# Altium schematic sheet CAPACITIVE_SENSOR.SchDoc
size A4; Revision: V1.2; SheetNumber: 4; SheetTotal: 10
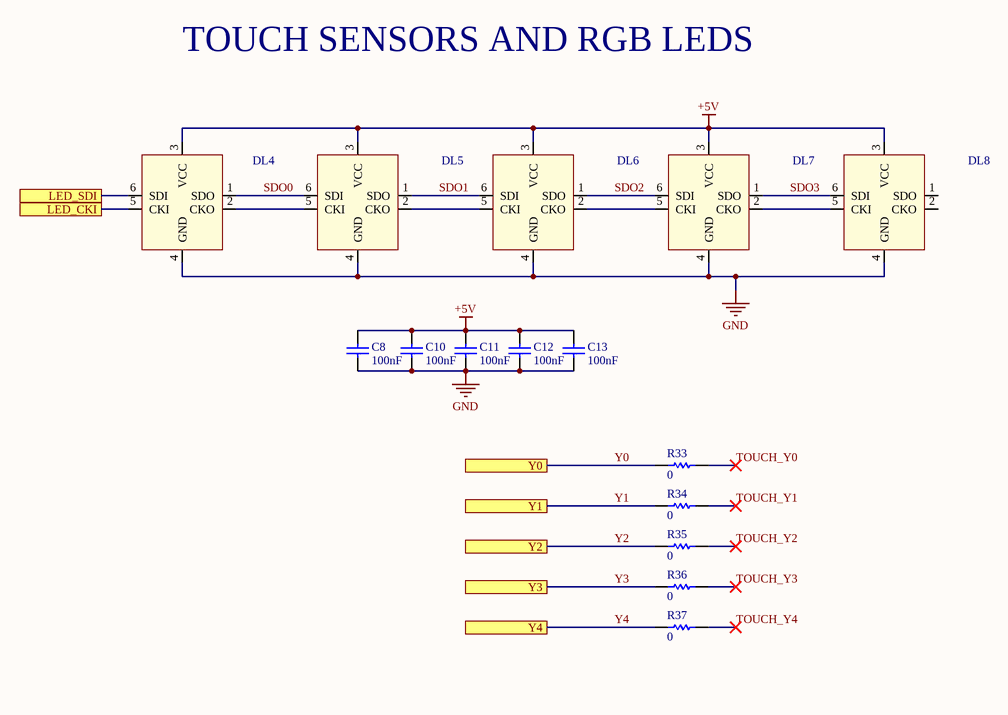
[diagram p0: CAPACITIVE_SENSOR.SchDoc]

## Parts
C8  value 100nF  [CAP-0402]  (hidden comment: GRM155R61H104KE19D)
C10  value 100nF  [CAP-0402]  (hidden comment: GRM155R61H104KE19D)
C11  value 100nF  [CAP-0402]  (hidden comment: GRM155R61H104KE19D)
C12  value 100nF  [CAP-0402]  (hidden comment: GRM155R61H104KE19D)
C13  value 100nF  [CAP-0402]  (hidden comment: GRM155R61H104KE19D)
DL4  APA1022020-2018  [APA102-2020-Footprint-1]  (value not drawn)
DL5  APA1022020-2018  [APA102-2020-Footprint-1]  (value not drawn)
DL6  APA1022020-2018  [APA102-2020-Footprint-1]  (value not drawn)
DL7  APA1022020-2018  [APA102-2020-Footprint-1]  (value not drawn)
DL8  APA1022020-2018  [APA102-2020-Footprint-1]  (value not drawn)
R33  value 0  [RES-0402]  (hidden comment: CRCW04020000Z0EDC)
R34  value 0  [RES-0402]  (hidden comment: CRCW04020000Z0EDC)
R35  value 0  [RES-0402]  (hidden comment: CRCW04020000Z0EDC)
R36  value 0  [RES-0402]  (hidden comment: CRCW04020000Z0EDC)
R37  value 0  [RES-0402]  (hidden comment: CRCW04020000Z0EDC)

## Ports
LED_CKI, LED_SDI, Y0, Y1, Y2, Y3, Y4

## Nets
+5V: C8.2 C10.2 C11.2 C12.2 C13.2 DL4.3(VCC) DL5.3(VCC) DL6.3(VCC) DL7.3(VCC) DL8.3(VCC)
GND: C8.1 C10.1 C11.1 C12.1 C13.1 DL4.4(GND) DL5.4(GND) DL6.4(GND) DL7.4(GND) DL8.4(GND)
LED_CKI: DL4.5(CKI) ; port LED_CKI
LED_SDI: DL4.6(SDI) ; port LED_SDI
SDO0: DL4.1(SDO) DL5.6(SDI)
SDO1: DL5.1(SDO) DL6.6(SDI)
SDO2: DL6.1(SDO) DL7.6(SDI)
SDO3: DL7.1(SDO) DL8.6(SDI)
TOUCH_Y0: R33.2
TOUCH_Y1: R34.2
TOUCH_Y2: R35.2
TOUCH_Y3: R36.2
TOUCH_Y4: R37.2
Y0: R33.1 ; port Y0
Y1: R34.1 ; port Y1
Y2: R35.1 ; port Y2
Y3: R36.1 ; port Y3
Y4: R37.1 ; port Y4
NetDL4_2: DL4.2(CKO) DL5.5(CKI)
NetDL5_2: DL5.2(CKO) DL6.5(CKI)
NetDL6_2: DL6.2(CKO) DL7.5(CKI)
NetDL7_2: DL7.2(CKO) DL8.5(CKI)

Not connected (* = marked no-connect by the designer): DL8 1(SDO) 2(CKO)

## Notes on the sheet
- TOUCH SENSORS AND RGB LEDS

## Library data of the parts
C8 C10-C13 = C0015-A.11: CAP CHIP 0402 100nF 50V X5R 10%; Manufacturer: Murata; Code Arduino: A5141
DL4-DL8 = L0003-A.8: LED RGB 2020; Manufacturer: Shenzhen LED Color Opto Electronic CO.,LTD.; Code Arduino: A5307
R33-R37 = R0000-A.11: RES CHIP 0402 0R 1/16W; Manufacturer: Vishay; Code Arduino: 0039; Power: 63mW; Tolerance: J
